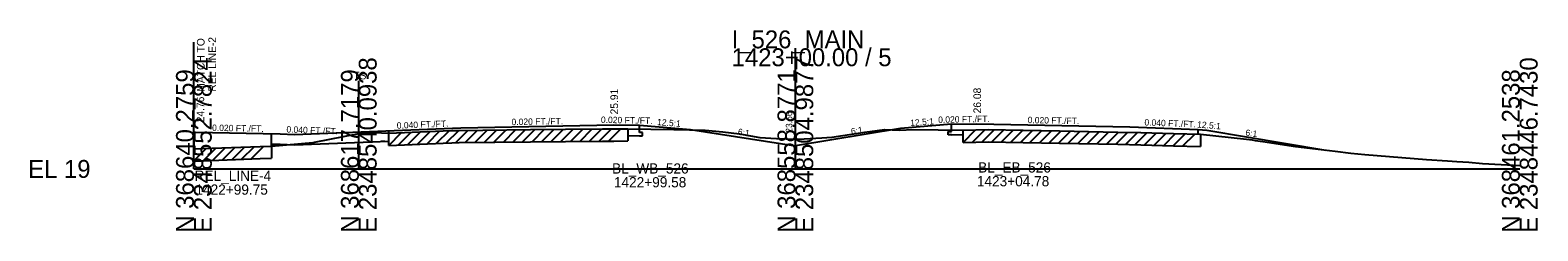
# Model space of a CAD drawing. Extents: x -170 to 2527928, y -10 to 1619750.
# Drawn here: x 3974.3 to 4210.9, y 2990.3 to 3021.7 of the extents above; entities that cross this region are included whole.
import ezdxf

# ---------------------------------------------------------------- set-up
doc = ezdxf.new("R2010")
doc.units = 0
for name, color, linetype in [('RD_GPK_XS_Cell', 7, 'Continuous'), ('RD_XS_Base', 7, 'Continuous'), ('RD_XS_EarthShd', 7, 'Continuous'), ('RD_XS_ExGround', 7, 'Continuous'), ('RD_XS_ExPaveRet', 7, 'Continuous'), ('RD_XS_MatchLine', 7, 'Continuous'), ('RD_XS_Pave', 7, 'Continuous'), ('RD_XS_PaveShd', 7, 'Continuous'), ('RD_XS_TieSlope', 7, 'Continuous'), ('RD_XS_TX_Elev_EX', 7, 'Continuous'), ('RD_XS_TX_Slope', 7, 'Continuous'), ('RD_XS_TX_Station', 7, 'Continuous')]:
    doc.layers.add(name, color=color, linetype=linetype)

msp = doc.modelspace()

# ---------------------------------------------------------------- linework, layer by layer
at = {"layer": 'RD_GPK_XS_Cell'}
for p, q in [((4094.4, 3000), (4094.4, 3018.89)), ((4000, 3000), (4025.88, 3000)), ((4025.88, 3000), (4094.4, 3000)), ((4094.4, 3000), (4208.08, 3000))]:
    msp.add_line(p, q, dxfattribs=at)
at = {"layer": 'RD_XS_Base'}
for p, q in [((4000, 3004.13), (4000, 3005.76)), ((4012.19, 3003.58), (4012.19, 3005.52)), ((4030.59, 3004.36), (4030.59, 3005.99)), ((4068.1, 3005.23), (4069.92, 3005.2)), ((4069.92, 3005.7), (4069.92, 3006.83)), ((4070.42, 3005.69), (4069.92, 3005.7)), ((4069.92, 3005.2), (4070.42, 3005.19)), ((4070.42, 3005.19), (4070.42, 3005.69)), ((4118.38, 3005.85), (4118.88, 3005.86)), ((4118.38, 3005.35), (4118.38, 3005.85)), ((4118.88, 3005.36), (4118.38, 3005.35)), ((4118.88, 3005.86), (4118.88, 3006.99)), ((4118.88, 3005.36), (4120.71, 3005.4)), ((4157.6, 3005.43), (4157.6, 3006.17)), ((4012.19, 3003.89), (4013.55, 3003.86)), ((4013.55, 3003.86), (4015.78, 3003.77)), ((4015.78, 3003.77), (4030.59, 3004.36)), ((4029.91, 3004.33), (4029.41, 3004.31))]:
    msp.add_line(p, q, dxfattribs=at)
at = {"layer": 'RD_XS_EarthShd'}
for p, q in [((4069.92, 3006.83), (4077.92, 3006.19)), ((4118.88, 3006.99), (4110.88, 3006.35))]:
    msp.add_line(p, q, dxfattribs=at)
at = {"layer": 'RD_XS_ExGround'}
msp.add_lwpolyline([(4000, 3003.16), (4001.34, 3003.21), (4010.39, 3003.53), (4012.19, 3003.58), (4018.67, 3004.15), (4018.73, 3004.15), (4018.93, 3004.19), (4025.88, 3005.53), (4026.75, 3005.7), (4029.43, 3005.63), (4030.59, 3005.6), (4039.12, 3005.97), (4040.46, 3006.03), (4041.62, 3006.04), (4052.82, 3006.18), (4058.33, 3006.23), (4064.14, 3006.27), (4065.92, 3006.27), (4068.1, 3006.3), (4075.34, 3006.15), (4080.24, 3006.05), (4083, 3005.8), (4085.63, 3005.48), (4088.8, 3004.93), (4091.45, 3004.78), (4094.4, 3004.66), (4094.82, 3004.64), (4098.56, 3004.87), (4100.11, 3004.98), (4105.28, 3005.76), (4108.39, 3006.19), (4110.74, 3006.09), (4112.86, 3006.16), (4120.71, 3006.08), (4122.72, 3006.12), (4124.65, 3006.16), (4130.15, 3006.06), (4135.87, 3005.95), (4145.01, 3005.78), (4148.59, 3005.71), (4153.75, 3005.55), (4157.95, 3005.42), (4165.2, 3004.65), (4166.07, 3004.55), (4166.58, 3004.47), (4167.74, 3004.29), (4172.86, 3003.53), (4179.13, 3002.76), (4181.55, 3002.46), (4183.79, 3002.27), (4193.46, 3001.5), (4196.73, 3001.26), (4198.21, 3001.16), (4200.08, 3001.05), (4202.25, 3000.85), (4208.08, 3000.55)], dxfattribs=at)
at = {"layer": 'RD_XS_ExPaveRet'}
for p, q in [((4030.59, 3003.68), (4032.59, 3005.69)), ((4030.59, 3003.68), (4030.59, 3005.6)), ((4032.09, 3003.75), (4034.09, 3005.75)), ((4033.59, 3003.81), (4035.59, 3005.81)), ((4035.09, 3003.88), (4037.09, 3005.88)), ((4036.59, 3003.94), (4038.59, 3005.94)), ((4038.09, 3004.01), (4040.1, 3006.01)), ((4039.59, 3004.07), (4041.56, 3006.04)), ((4041.09, 3004.12), (4043.03, 3006.06)), ((4042.59, 3004.14), (4044.53, 3006.08)), ((4044.09, 3004.15), (4046.03, 3006.09)), ((4045.59, 3004.17), (4047.53, 3006.11)), ((4047.09, 3004.19), (4049.03, 3006.13)), ((4048.59, 3004.21), (4050.53, 3006.15)), ((4050.09, 3004.23), (4052.03, 3006.17)), ((4051.59, 3004.24), (4053.53, 3006.18)), ((4053.09, 3004.26), (4055.03, 3006.2)), ((4054.59, 3004.27), (4056.53, 3006.21)), ((4056.09, 3004.29), (4058.03, 3006.22)), ((4057.59, 3004.3), (4059.52, 3006.23)), ((4059.09, 3004.31), (4061.02, 3006.24)), ((4060.59, 3004.32), (4062.52, 3006.26)), ((4062.09, 3004.34), (4064.02, 3006.27)), ((4063.59, 3004.35), (4065.52, 3006.27)), ((4065.09, 3004.35), (4067.02, 3006.28)), ((4068.1, 3006.3), (4068.1, 3004.38)), ((4120.71, 3004.16), (4122.67, 3006.12)), ((4120.71, 3004.16), (4120.71, 3006.08)), ((4122.21, 3004.19), (4124.17, 3006.15)), ((4123.71, 3004.22), (4125.63, 3006.15)), ((4125.21, 3004.24), (4127.09, 3006.12)), ((4126.71, 3004.21), (4128.59, 3006.09)), ((4128.21, 3004.18), (4130.09, 3006.06)), ((4129.71, 3004.15), (4131.59, 3006.04)), ((4131.21, 3004.13), (4133.09, 3006.01)), ((4132.71, 3004.1), (4134.59, 3005.98)), ((4134.21, 3004.07), (4136.09, 3005.95)), ((4135.71, 3004.04), (4137.59, 3005.92)), ((4137.21, 3004.01), (4139.09, 3005.89)), ((4138.71, 3003.98), (4140.59, 3005.86)), ((4140.21, 3003.95), (4142.09, 3005.83)), ((4141.71, 3003.92), (4143.59, 3005.8)), ((4143.21, 3003.89), (4145.09, 3005.77)), ((4144.71, 3003.86), (4146.59, 3005.75)), ((4146.21, 3003.84), (4148.09, 3005.72)), ((4147.71, 3003.81), (4149.58, 3005.68)), ((4149.21, 3003.77), (4151.07, 3005.63)), ((4150.71, 3003.72), (4152.57, 3005.58)), ((4152.21, 3003.68), (4154.07, 3005.54)), ((4153.71, 3003.63), (4155.57, 3005.49)), ((4155.21, 3003.59), (4157.07, 3005.45)), ((4157.95, 3005.42), (4157.95, 3003.51)), ((4000, 3001.24), (4001.99, 3003.23)), ((4000, 3001.24), (4000, 3003.16)), ((4001.5, 3001.3), (4003.49, 3003.29)), ((4003, 3001.35), (4004.99, 3003.34)), ((4004.5, 3001.4), (4006.49, 3003.39)), ((4006, 3001.46), (4007.99, 3003.44)), ((4007.5, 3001.51), (4009.49, 3003.5)), ((4009, 3001.56), (4010.98, 3003.55)), ((4012.19, 3003.58), (4012.19, 3001.67)), ((4030.59, 3003.68), (4039.12, 3004.05)), ((4039.12, 3004.05), (4040.46, 3004.11)), ((4040.46, 3004.11), (4041.62, 3004.12)), ((4041.62, 3004.12), (4052.82, 3004.26)), ((4052.82, 3004.26), (4058.33, 3004.31)), ((4058.33, 3004.31), (4064.14, 3004.35)), ((4064.14, 3004.35), (4065.92, 3004.36)), ((4065.92, 3004.36), (4068.1, 3004.38)), ((4120.71, 3004.16), (4122.72, 3004.2)), ((4122.72, 3004.2), (4124.65, 3004.25)), ((4124.65, 3004.25), (4130.15, 3004.15)), ((4130.15, 3004.15), (4135.87, 3004.03)), ((4135.87, 3004.03), (4145.01, 3003.86)), ((4145.01, 3003.86), (4148.59, 3003.79)), ((4148.59, 3003.79), (4153.75, 3003.63)), ((4153.75, 3003.63), (4157.95, 3003.51)), ((4000, 3001.24), (4001.34, 3001.29)), ((4001.34, 3001.29), (4010.39, 3001.61)), ((4010.39, 3001.61), (4012.19, 3001.67))]:
    msp.add_line(p, q, dxfattribs=at)
at = {"layer": 'RD_XS_MatchLine'}
for p, q in [((4000, 3000), (4000, 3019.86)), ((4025.88, 3000), (4025.88, 3013.78))]:
    msp.add_line(p, q, dxfattribs=at)
at = {"layer": 'RD_XS_Pave'}
for p, q in [((4000, 3005.76), (4000.25, 3005.76)), ((4000.25, 3005.76), (4013.55, 3005.49)), ((4041.92, 3006.44), (4065.92, 3006.91)), ((4122.88, 3007.08), (4146.88, 3006.6))]:
    msp.add_line(p, q, dxfattribs=at)
at = {"layer": 'RD_XS_PaveShd'}
for p, q in [((4000, 3005.76), (4000, 3003.16)), ((4013.55, 3005.49), (4015.78, 3005.4)), ((4015.78, 3005.4), (4041.92, 3006.44)), ((4065.92, 3006.91), (4069.92, 3006.83)), ((4118.88, 3006.99), (4122.88, 3007.08)), ((4146.88, 3006.6), (4157.6, 3006.17))]:
    msp.add_line(p, q, dxfattribs=at)
at = {"layer": 'RD_XS_TieSlope'}
for p, q in [((4077.92, 3006.19), (4094.4, 3003.61)), ((4110.88, 3006.35), (4094.4, 3003.61)), ((4157.6, 3006.17), (4158.98, 3006.06)), ((4158.98, 3006.06), (4177.67, 3002.95))]:
    msp.add_line(p, q, dxfattribs=at)

# ---------------------------------------------------------------- texts
at = {"layer": 'RD_GPK_XS_Cell'}
for s, p in [('I_526_MAIN', (4084.4, 3018.89)), ('1423+00.00 / 5', (4084.4, 3016.09)), ('EL 19', (3974, 2998.6))]:
    msp.add_text(s, height=2.8, dxfattribs=at).set_placement(p)
for s, p in [('E 2348552.7824', (4002.8, 2990)), ('E 2348540.0938', (4028.68, 2990)), ('E 2348504.9877', (4097.2, 2990)), ('E 2348446.7430', (4210.88, 2990)), ('N 368640.2759', (4000, 2990)), ('N 368617.7179', (4025.88, 2990)), ('N 368558.8771', (4094.4, 2990)), ('N 368461.2538', (4208.08, 2990))]:
    msp.add_text(s, height=2.8, rotation=90, dxfattribs=at).set_placement(p)
at = {"layer": 'RD_XS_MatchLine'}
msp.add_text('TS', height=1.2, dxfattribs=at).set_placement((4025.02, 3014.03))
at = {"layer": 'RD_XS_TX_Elev_EX'}
msp.add_text('23.66', height=1, rotation=90, dxfattribs=at).set_placement((4093.9, 3005.66))
at = {"layer": 'RD_XS_TX_Slope'}
for s, rotation, p in [('0.040 FT./FT.', 2.2732, (4031.86, 3006.29)), ('0.020 FT./FT.', 1.1284, (4049.86, 3006.85)), ('0.020 FT./FT.', 358.8371, (4063.87, 3007.21)), ('12.5:1', 355.4261, (4072.67, 3006.87)), ('12.5:1', 4.5739, (4112.46, 3006.69)), ('0.020 FT./FT.', 1.1621, (4116.82, 3007.2)), ('0.020 FT./FT.', 358.8708, (4130.84, 3007.17)), ('0.040 FT./FT.', 357.7094, (4149.16, 3006.81)), ('12.5:1', 355.4261, (4157.42, 3006.48)), ('0.020 FT./FT.', 358.8542, (4002.85, 3005.96)), ('0.040 FT./FT.', 357.7094, (4014.51, 3005.71)), ('6:1', 350.5377, (4085.31, 3005.36)), ('6:1', 9.4623, (4103.21, 3005.36)), ('6:1', 352.6182, (4164.98, 3005.21))]:
    msp.add_text(s, height=1, rotation=rotation, dxfattribs=at).set_placement(p)
at = {"layer": 'RD_XS_TX_Station'}
for s, p in [('MATCH TO', (4001.68, 3012.1)), ('REL LINE-2', (4003.48, 3012.1)), (' 25.91', (4066.57, 3008.09)), (' 26.08', (4123.54, 3008.25)), (' 24.76', (4001.62, 3006.86))]:
    msp.add_text(s, height=1.2, rotation=90, dxfattribs=at).set_placement(p)
for s, p in [('BL_WB_526', (4065.63, 2999.27)), ('BL_EB_526', (4123.08, 2999.43)), ('REL_LINE-4', (4000.12, 2998.13)), ('1422+99.58', (4065.92, 2997.11)), ('1423+04.78', (4122.88, 2997.28)), ('1422+99.75', (4000.25, 2995.96))]:
    msp.add_text(s, height=1.6, dxfattribs=at).set_placement(p)

doc.saveas('drawing.dxf')
